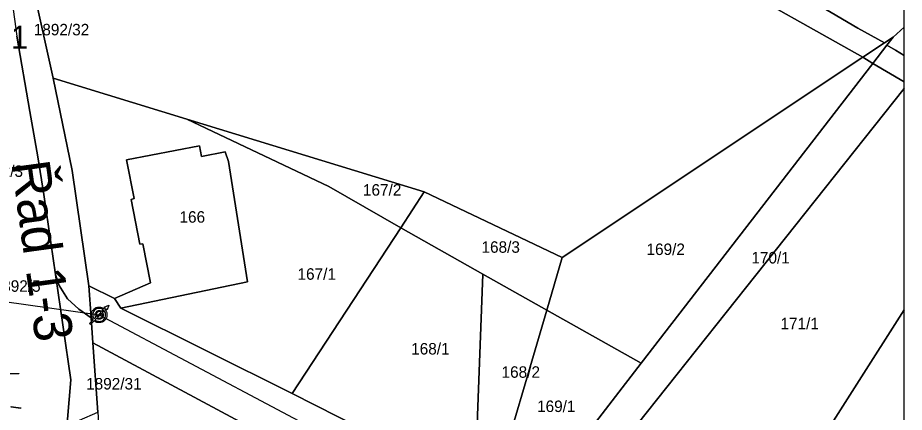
# Model space of a CAD drawing. Extents: x -559956 to -559707, y -1077221 to -1076919.
# Drawn here: x -559822.9 to -559707, y -1077037.9 to -1076986.4 of the extents above; entities that cross this region are included whole.
import ezdxf

# ---------------------------------------------------------------- set-up
doc = ezdxf.new("R2010")
doc.units = 0
for name, color, linetype in [('Armatura vodovodní', 7, 'Continuous'), ('Odběrné místo', 7, 'Continuous'), ('Označení hydrantu', 7, 'Continuous'), ('Parcela-polygon', 7, 'Continuous'), ('Parcela-text', 7, 'Continuous'), ('Vodovodní přípojka', 7, 'Continuous'), ('Řad vodovodní označení', 7, 'Continuous')]:
    doc.layers.add(name, color=color, linetype=linetype)

msp = doc.modelspace()

# ---------------------------------------------------------------- linework, layer by layer
at = {"layer": 'Armatura vodovodní'}
for points in [[(-559823.94, -1077032.88), (-559822.69, -1077032.85), (-559822.69, -1077032.93), (-559823.94, -1077032.96), (-559823.94, -1077032.88)], [(-559823.71, -1077037.18), (-559822.47, -1077037.37), (-559822.48, -1077037.45), (-559823.72, -1077037.26), (-559823.71, -1077037.18)]]:
    msp.add_lwpolyline(points, dxfattribs=at)
at = {"layer": 'Odběrné místo'}
for points in [[(-559811.43, -1077024.32), (-559811.55, -1077024.21), (-559810.96, -1077023.97), (-559811.19, -1077024.55), (-559811.32, -1077024.42), (-559811.45, -1077024.55)], [(-559812.54, -1077025.43), (-559811.97, -1077024.86)], [(-559811.88, -1077024.99), (-559812.45, -1077025.56)], [(-559811.88, -1077024.77), (-559811.68, -1077024.57)], [(-559811.57, -1077024.67), (-559811.78, -1077024.88)], [(-559811.56, -1077024.45), (-559811.43, -1077024.32)], [(-559812.87, -1077025.98), (-559813.36, -1077026.47), (-559813.46, -1077026.36), (-559812.98, -1077025.87)], [(-559812.86, -1077025.75), (-559812.64, -1077025.53)], [(-559812.54, -1077025.65), (-559812.75, -1077025.86)]]:
    msp.add_lwpolyline(points, dxfattribs=at)
for points in [[(-559812.98, -1077025.87), (-559813.22, -1077025.59), (-559813.22, -1077025.22), (-559813.22, -1077024.8), (-559812.92, -1077024.51), (-559812.63, -1077024.21), (-559812.21, -1077024.21), (-559811.84, -1077024.21), (-559811.56, -1077024.45)], [(-559811.68, -1077024.57), (-559811.91, -1077024.38), (-559812.21, -1077024.38), (-559812.56, -1077024.38), (-559812.81, -1077024.62), (-559813.05, -1077024.87), (-559813.05, -1077025.22), (-559813.05, -1077025.52), (-559812.86, -1077025.75)], [(-559811.45, -1077024.55), (-559811.2, -1077024.83), (-559811.2, -1077025.22), (-559811.2, -1077025.64), (-559811.5, -1077025.93), (-559811.79, -1077026.23), (-559812.21, -1077026.23), (-559812.59, -1077026.23), (-559812.87, -1077025.98)], [(-559812.75, -1077025.86), (-559812.52, -1077026.06), (-559812.21, -1077026.06), (-559811.86, -1077026.06), (-559811.62, -1077025.81), (-559811.37, -1077025.57), (-559811.37, -1077025.22), (-559811.37, -1077024.9), (-559811.57, -1077024.67)], [(-559812.64, -1077025.53), (-559812.65, -1077025.51), (-559812.66, -1077025.5), (-559812.72, -1077025.37), (-559812.72, -1077025.23), (-559812.72, -1077024.96), (-559812.57, -1077024.81), (-559812.43, -1077024.66), (-559812.2, -1077024.66), (-559812.06, -1077024.66), (-559811.94, -1077024.73), (-559811.91, -1077024.75), (-559811.88, -1077024.77)], [(-559811.97, -1077024.86), (-559811.99, -1077024.85), (-559812.01, -1077024.84), (-559812.1, -1077024.78), (-559812.2, -1077024.78), (-559812.35, -1077024.78), (-559812.46, -1077024.89), (-559812.57, -1077024.99), (-559812.57, -1077025.23), (-559812.57, -1077025.34), (-559812.54, -1077025.43)], [(-559811.78, -1077024.88), (-559811.76, -1077024.91), (-559811.75, -1077024.93), (-559811.69, -1077025.06), (-559811.69, -1077025.22), (-559811.69, -1077025.38), (-559811.76, -1077025.51), (-559811.82, -1077025.64), (-559811.94, -1077025.71), (-559812.06, -1077025.77), (-559812.2, -1077025.77), (-559812.36, -1077025.77), (-559812.48, -1077025.7), (-559812.51, -1077025.68), (-559812.54, -1077025.65)], [(-559812.45, -1077025.56), (-559812.35, -1077025.65), (-559812.21, -1077025.65), (-559812.04, -1077025.65), (-559811.94, -1077025.54), (-559811.84, -1077025.42), (-559811.84, -1077025.22), (-559811.84, -1077025.09), (-559811.88, -1077024.99), (-559811.88, -1077024.99), (-559811.88, -1077024.99)]]:
    msp.add_open_spline(points, degree=3, dxfattribs=at)
at = {"layer": 'Parcela-polygon'}
for p, q in [((-559707.02, -1076987.64), (-559707.02, -1076918.77)), ((-559707.02, -1076991.35), (-559707.02, -1076987.64)), ((-559707.02, -1076994.78), (-559707.02, -1076991.35)), ((-559707.02, -1076995.64), (-559707.02, -1076994.78)), ((-559707.02, -1077024.54), (-559707.02, -1076995.64)), ((-559707.02, -1077045.12), (-559707.02, -1077024.54))]:
    msp.add_line(p, q, dxfattribs=at)
for points in [[(-559817.45, -1076918.77), (-559819.31, -1076927.58), (-559819.52, -1076929.72), (-559789.34, -1076946.47), (-559756.49, -1076962.53), (-559740.76, -1076971.23), (-559729.78, -1076977.96), (-559713.09, -1076987.78), (-559709.61, -1076989.7), (-559708.48, -1076988.95), (-559707.02, -1076987.64)], [(-559707.02, -1076987.64), (-559708.48, -1076988.95), (-559709.28, -1076989.99), (-559708.18, -1076990.64), (-559707.02, -1076991.35)], [(-559823.32, -1077073.15), (-559821.04, -1077065.52), (-559820.03, -1077061.65), (-559819.41, -1077058.74), (-559816.6, -1077041.94), (-559815.93, -1077033.69), (-559817.92, -1077019.93), (-559819.43, -1077009.52), (-559820.21, -1077004.57), (-559821.27, -1076998.68), (-559822.96, -1076988.81)], [(-559707.02, -1076991.35), (-559708.18, -1076990.64), (-559709.28, -1076989.99), (-559711.14, -1076992.39), (-559707.02, -1076994.78)], [(-559707.02, -1076994.78), (-559711.14, -1076992.39), (-559741.39, -1077031.54), (-559757.43, -1077052.31), (-559753.56, -1077054.16), (-559707.02, -1076995.64)], [(-559707.02, -1076995.64), (-559753.56, -1077054.16), (-559732.09, -1077063.84), (-559707.02, -1077024.54)], [(-559707.02, -1077024.54), (-559732.09, -1077063.84), (-559737.55, -1077070.66), (-559748, -1077091.24), (-559761.93, -1077116.33), (-559776.08, -1077141.84), (-559781.47, -1077152.19), (-559794.21, -1077176.64), (-559804.13, -1077198.3), (-559804.99, -1077200.42), (-559813.55, -1077221.34)]]:
    msp.add_lwpolyline(points, dxfattribs=at)
for points in [[(-559820.03, -1076934.98), (-559790.36, -1076949.92), (-559754.85, -1076967.72), (-559750.31, -1076970.28), (-559712.43, -1076991.58), (-559709.61, -1076989.7), (-559713.09, -1076987.78), (-559729.78, -1076977.96), (-559740.76, -1076971.23), (-559756.49, -1076962.53), (-559789.34, -1076946.47), (-559819.52, -1076929.72)], [(-559824.5, -1076951.91), (-559824.93, -1076960.91), (-559824.89, -1076969.92), (-559824.18, -1076979.89), (-559822.96, -1076988.81), (-559821.27, -1076998.68), (-559820.21, -1077004.57), (-559819.43, -1077009.52), (-559817.92, -1077019.93), (-559817.45, -1077021.39), (-559816.36, -1077023.11), (-559814.85, -1077024.48), (-559813.27, -1077025.59), (-559813.57, -1077021.42), (-559815.76, -1077006.35), (-559818.24, -1076994.33), (-559822.2, -1076976.41), (-559821.95, -1076954.78), (-559820.03, -1076934.98), (-559822.57, -1076933.71), (-559823.69, -1076942.95)], [(-559790.36, -1076949.92), (-559820.03, -1076934.98), (-559821.95, -1076954.78), (-559822.2, -1076976.41), (-559818.24, -1076994.33), (-559800.74, -1076999.68), (-559769.74, -1077009.16), (-559751.72, -1077017.71), (-559712.43, -1076991.58), (-559750.31, -1076970.28), (-559754.85, -1076967.72)], [(-559708.48, -1076988.95), (-559709.61, -1076989.7), (-559712.43, -1076991.58), (-559711.14, -1076992.39), (-559709.28, -1076989.99)], [(-559711.14, -1076992.39), (-559712.43, -1076991.58), (-559751.72, -1077017.71), (-559753.73, -1077024.58), (-559741.39, -1077031.54)], [(-559792.82, -1077020.91), (-559809.39, -1077024.33), (-559787.01, -1077035.47), (-559772.81, -1077013.84), (-559782.2, -1077008.44), (-559800.74, -1076999.68), (-559818.24, -1076994.33), (-559815.76, -1077006.35), (-559813.57, -1077021.42), (-559810.22, -1077023.06), (-559805.51, -1077021.03), (-559806.51, -1077015.92), (-559806.9, -1077015.97), (-559808.04, -1077010.16), (-559807.66, -1077010.04), (-559808.65, -1077004.97), (-559799.11, -1077003.15), (-559798.84, -1077004.54), (-559795.73, -1077003.92), (-559795.32, -1077005.21)], [(-559769.74, -1077009.16), (-559800.74, -1076999.68), (-559782.2, -1077008.44), (-559772.81, -1077013.84)], [(-559810.22, -1077023.06), (-559809.39, -1077024.33), (-559792.82, -1077020.91), (-559795.32, -1077005.21), (-559795.73, -1077003.92), (-559798.84, -1077004.54), (-559799.11, -1077003.15), (-559808.65, -1077004.97), (-559807.66, -1077010.04), (-559808.04, -1077010.16), (-559806.9, -1077015.97), (-559806.51, -1077015.92), (-559805.51, -1077021.03)], [(-559769.74, -1077009.16), (-559772.81, -1077013.84), (-559762.08, -1077019.88), (-559753.73, -1077024.58), (-559751.72, -1077017.71)], [(-559772.81, -1077013.84), (-559787.01, -1077035.47), (-559763.12, -1077047.57), (-559762.08, -1077019.88)], [(-559815.93, -1077033.69), (-559816.6, -1077041.94), (-559816.13, -1077040.49), (-559814.79, -1077038.97), (-559812.41, -1077037.94), (-559813.04, -1077028.88), (-559813.27, -1077025.59), (-559814.85, -1077024.48), (-559816.36, -1077023.11), (-559817.45, -1077021.39), (-559817.92, -1077019.93)], [(-559763.12, -1077047.57), (-559760.82, -1077048.73), (-559753.73, -1077024.58), (-559762.08, -1077019.88)], [(-559787.01, -1077035.47), (-559809.39, -1077024.33), (-559810.22, -1077023.06), (-559813.57, -1077021.42), (-559813.27, -1077025.59), (-559813.04, -1077028.88), (-559761.95, -1077056.26), (-559756.94, -1077058.73), (-559749.38, -1077063.1), (-559740.18, -1077067.86), (-559737.55, -1077070.66), (-559732.09, -1077063.84), (-559753.56, -1077054.16), (-559757.43, -1077052.31), (-559760.82, -1077048.73), (-559763.12, -1077047.57)], [(-559753.73, -1077024.58), (-559760.82, -1077048.73), (-559757.43, -1077052.31), (-559741.39, -1077031.54)], [(-559737.55, -1077070.66), (-559740.18, -1077067.86), (-559749.38, -1077063.1), (-559756.94, -1077058.73), (-559761.95, -1077056.26), (-559813.04, -1077028.88), (-559812.41, -1077037.94), (-559812.17, -1077041.3), (-559802.73, -1077041.45), (-559763.29, -1077057.42), (-559758.48, -1077060.82), (-559745.46, -1077066.94)]]:
    msp.add_lwpolyline(points, close=True, dxfattribs=at)
at = {"layer": 'Vodovodní přípojka'}
msp.add_line((-559824.88, -1077023.43), (-559812.21, -1077025.22), dxfattribs=at)
msp.add_lwpolyline([(-559812.21, -1077025.22), (-559740.37, -1077063.33), (-559742.92, -1077070.61), (-559742.92, -1077076.8), (-559767.64, -1077122.16), (-559773.1, -1077118.25)], dxfattribs=at)

# ---------------------------------------------------------------- texts
at = {"layer": 'Označení hydrantu'}
msp.add_text('H11', height=3, dxfattribs=at).set_placement((-559828.86, -1076990.46))
at = {"layer": 'Parcela-text'}
for s, p in [('1892/32', (-559820.76, -1076988.72)), ('1892/3', (-559828.3, -1077007.2)), ('167/2', (-559777.75, -1077009.65)), ('166', (-559801.72, -1077013.18)), ('168/3', (-559762.26, -1077017.11)), ('169/2', (-559740.7, -1077017.4)), ('170/1', (-559727, -1077018.5)), ('167/1', (-559786.3, -1077020.63)), ('1892/5', (-559826, -1077022.2)), ('171/1', (-559723.2, -1077027.1)), ('168/1', (-559771.45, -1077030.39)), ('168/2', (-559759.64, -1077033.43)), ('1892/31', (-559813.92, -1077034.96)), ('169/1', (-559755, -1077037.9))]:
    msp.add_text(s, height=1.5, dxfattribs=at).set_placement(p)
at = {"layer": 'Řad vodovodní označení'}
msp.add_text('Řad 1-3', height=5, rotation=277.7613, dxfattribs=at).set_placement((-559823.7, -1077005.38))

doc.saveas('drawing.dxf')
